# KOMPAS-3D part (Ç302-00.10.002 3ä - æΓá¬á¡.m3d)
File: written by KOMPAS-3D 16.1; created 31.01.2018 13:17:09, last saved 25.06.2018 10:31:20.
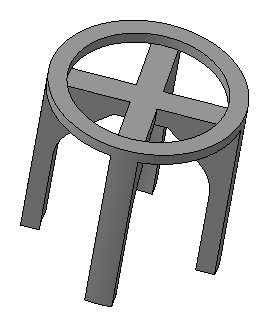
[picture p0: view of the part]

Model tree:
1. Эскиз:1
2. Операция вращения:1
     Угол 1 = 360
3. Эскиз:4
4. Операция выдавливания:3
     Расстояние 1 = 3.5; Расстояние 2 = 160
5. Эскиз:3
6. Вырезать элемент выдавливания:1
7. Массив по концентрической сетке:2  (with: Вырезать элемент выдавливания:1, Эскиз:3)  (4 pattern instances)
     Геометрический массив = 3; Шаг 2 = 360
8. Эскиз:5
9. Вырезать элемент выдавливания:2
     Расстояние 1 = 2
10. Фаска:1
     Угол = 45; Длина 1 = 1; Длина 2 = 1
11. Скругление:1
     Радиус = 15
12. Эскиз:8
13. Операция выдавливания:4
     Расстояние 1 = 10; Расстояние 2 = 6
14. Эскиз:7
15. Сечение поверхностью:1  (labels: А302-00.10.002 3Д)

Expressions: v184+10; 57.50+1-3
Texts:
  Линейный размер с обрывом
